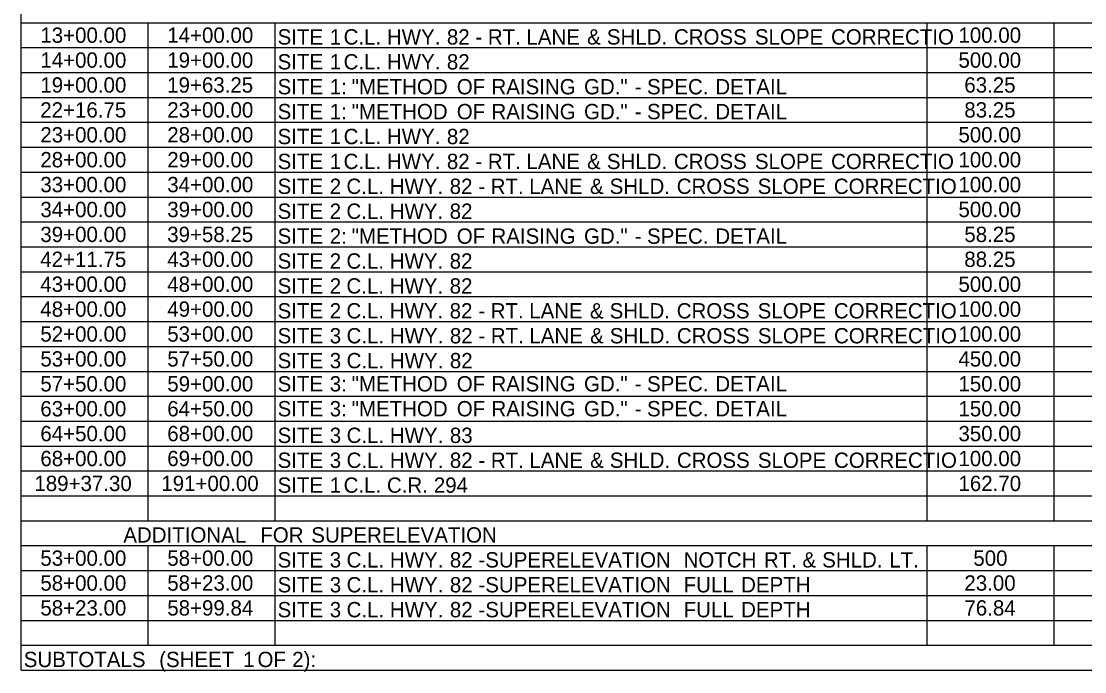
# Model space of a CAD drawing. Extents: x 977434 to 989596, y 1525697 to 1528336.
# Drawn here: x 982704.7 to 983038, y 1527610 to 1527813.7 of the extents above; entities that cross this region are included whole.
import ezdxf

# ---------------------------------------------------------------- set-up
doc = ezdxf.new("R2010")
doc.units = 0
doc.layers.add('Default', color=7, linetype='Continuous')

msp = doc.modelspace()

# ---------------------------------------------------------------- linework, layer by layer
at = {"layer": 'Default'}
for p, q in [((982704.74, 1527610.44), (982704.74, 1528101.06)), ((982704.74, 1527610.44), (982704.74, 1528101.06)), ((982704.74, 1527813.24), (984062.72, 1527813.24)), ((982744.52, 1527657.24), (982744.52, 1527813.24)), ((982744.52, 1527657.24), (982744.52, 1527813.24)), ((982784.3, 1527813.24), (982988.66, 1527813.24)), ((982784.3, 1527657.24), (982784.3, 1527813.24)), ((982784.3, 1527657.24), (982784.3, 1527813.24)), ((982988.66, 1527657.24), (982988.66, 1527813.24)), ((982988.66, 1527657.24), (982988.66, 1527813.24)), ((983028.44, 1527657.24), (983028.44, 1527813.24)), ((983028.44, 1527657.24), (983028.44, 1527813.24)), ((982704.74, 1527805.44), (984062.72, 1527805.44)), ((982704.74, 1527797.64), (984062.72, 1527797.64)), ((982704.74, 1527789.84), (984062.72, 1527789.84)), ((982704.74, 1527782.04), (984062.72, 1527782.04)), ((982704.74, 1527774.24), (984062.72, 1527774.24)), ((982704.74, 1527766.44), (984062.72, 1527766.44)), ((982704.74, 1527758.64), (984062.72, 1527758.64)), ((982704.74, 1527750.84), (984062.72, 1527750.84)), ((982704.74, 1527743.04), (984062.72, 1527743.04)), ((982704.74, 1527735.24), (984062.72, 1527735.24)), ((982704.74, 1527727.44), (984062.72, 1527727.44)), ((982704.74, 1527719.64), (984062.72, 1527719.64)), ((982704.74, 1527711.84), (984062.72, 1527711.84)), ((982704.74, 1527704.04), (984062.72, 1527704.04)), ((982704.74, 1527696.24), (984062.72, 1527696.24)), ((982704.74, 1527688.44), (984062.72, 1527688.44)), ((982704.74, 1527680.64), (984062.72, 1527680.64)), ((982704.74, 1527672.84), (984062.72, 1527672.84)), ((982704.74, 1527665.04), (984062.72, 1527665.04)), ((982704.74, 1527657.24), (983108, 1527657.24)), ((982704.74, 1527657.24), (984062.72, 1527657.24)), ((982704.74, 1527649.44), (984062.72, 1527649.44)), ((982744.52, 1527618.24), (982744.52, 1527649.44)), ((982744.52, 1527618.24), (982744.52, 1527649.44)), ((982784.3, 1527618.24), (982784.3, 1527649.44)), ((982784.3, 1527618.24), (982784.3, 1527649.44)), ((982988.66, 1527618.24), (982988.66, 1527649.44)), ((982988.66, 1527618.24), (982988.66, 1527649.44)), ((983028.44, 1527618.24), (983028.44, 1527649.44)), ((983028.44, 1527618.24), (983028.44, 1527649.44)), ((982704.74, 1527641.64), (984062.72, 1527641.64)), ((982704.74, 1527633.84), (984062.72, 1527633.84)), ((982704.74, 1527626.04), (984062.72, 1527626.04)), ((982704.74, 1527618.24), (984062.72, 1527618.24)), ((982704.74, 1527610.44), (984062.72, 1527610.44))]:
    msp.add_line(p, q, dxfattribs=at)

# ---------------------------------------------------------------- texts
for s, p in [('13+00.00', (982710.72, 1527806.94)), ('14+00.00', (982750.5, 1527806.94)), ('SITE', (982785.08, 1527806.4)), (' C.L.', (982803.99, 1527806.4)), (' 82', (982836.35, 1527806.4)), (' SHLD.', (982886.48, 1527806.4)), (' CROSS', (982907.51, 1527806.4)), (' SLOPE', (982932.88, 1527806.4)), (' CORRECTIO', (982956.75, 1527806.4)), ('100.00', (982998.46, 1527806.94)), (' 1', (982799.63, 1527806.4)), (' HWY.', (982817.56, 1527806.4)), (' -', (982845.31, 1527806.4)), (' RT.', (982849.2, 1527806.4)), (' LANE', (982861.28, 1527806.4)), (' &', (982880.3, 1527806.4)), ('14+00.00', (982710.72, 1527799.14)), ('19+00.00', (982750.5, 1527799.14)), ('SITE', (982785.08, 1527798.6)), (' 1', (982799.63, 1527798.6)), (' C.L.', (982803.99, 1527798.6)), (' HWY.', (982817.56, 1527798.6)), (' 82', (982836.35, 1527798.6)), ('500.00', (982998.46, 1527799.14)), ('19+00.00', (982710.72, 1527791.34)), ('19+63.25', (982750.47, 1527791.34)), ('SITE', (982785.08, 1527790.8)), (' 1:', (982799.63, 1527790.8)), (' "METHOD', (982806.5, 1527790.8)), (' OF', (982839.45, 1527790.8)), (' RAISING', (982850.32, 1527790.8)), (' GD."', (982879.33, 1527790.8)), (' SPEC.', (982899.07, 1527790.8)), (' DETAIL', (982920.48, 1527790.8)), ('63.25', (983000.3, 1527791.34)), (' -', (982895.19, 1527790.8)), ('22+16.75', (982710.69, 1527783.54)), ('23+00.00', (982750.5, 1527783.54)), ('83.25', (983000.3, 1527783.54)), ('SITE', (982785.08, 1527783)), (' 1:', (982799.63, 1527783)), (' "METHOD', (982806.5, 1527783)), (' OF', (982839.45, 1527783)), (' RAISING', (982850.32, 1527783)), (' GD."', (982879.33, 1527783)), (' -', (982895.19, 1527783)), (' SPEC.', (982899.07, 1527783)), (' DETAIL', (982920.48, 1527783)), ('23+00.00', (982710.72, 1527775.74)), ('28+00.00', (982750.5, 1527775.74)), ('SITE', (982785.08, 1527775.2)), (' 1', (982799.63, 1527775.2)), (' C.L.', (982803.99, 1527775.2)), (' HWY.', (982817.56, 1527775.2)), (' 82', (982836.35, 1527775.2)), ('500.00', (982998.46, 1527775.74)), ('28+00.00', (982710.72, 1527767.94)), ('29+00.00', (982750.5, 1527767.94)), ('SITE', (982785.08, 1527767.4)), (' 1', (982799.63, 1527767.4)), (' C.L.', (982803.99, 1527767.4)), (' HWY.', (982817.56, 1527767.4)), (' 82', (982836.35, 1527767.4)), (' RT.', (982849.2, 1527767.4)), (' LANE', (982861.28, 1527767.4)), (' &', (982880.3, 1527767.4)), (' SHLD.', (982886.48, 1527767.4)), (' CROSS', (982907.51, 1527767.4)), (' SLOPE', (982932.88, 1527767.4)), (' CORRECTIO', (982956.75, 1527767.4)), ('100.00', (982998.46, 1527767.94)), (' -', (982845.31, 1527767.4)), ('33+00.00', (982710.72, 1527760.14)), ('34+00.00', (982750.5, 1527760.14)), ('100.00', (982998.46, 1527760.14)), ('SITE', (982785.08, 1527759.6)), (' 2', (982799.63, 1527759.6)), (' C.L.', (982804.87, 1527759.6)), (' HWY.', (982818.44, 1527759.6)), (' 82', (982837.22, 1527759.6)), (' -', (982846.19, 1527759.6)), (' RT.', (982850.07, 1527759.6)), (' LANE', (982862.15, 1527759.6)), (' &', (982881.18, 1527759.6)), (' SHLD.', (982887.36, 1527759.6)), (' CROSS', (982908.39, 1527759.6)), (' SLOPE', (982933.76, 1527759.6)), (' CORRECTIO', (982957.63, 1527759.6)), ('34+00.00', (982710.72, 1527752.34)), ('39+00.00', (982750.5, 1527752.34)), ('SITE', (982785.08, 1527751.8)), (' 2', (982799.63, 1527751.8)), (' C.L.', (982804.87, 1527751.8)), (' HWY.', (982818.44, 1527751.8)), (' 82', (982837.22, 1527751.8)), ('500.00', (982998.46, 1527752.34)), ('39+00.00', (982710.72, 1527744.54)), ('39+58.25', (982750.47, 1527744.54)), ('SITE', (982785.08, 1527744)), (' 2:', (982799.63, 1527744)), (' "METHOD', (982806.5, 1527744)), (' OF', (982839.45, 1527744)), (' RAISING', (982850.32, 1527744)), (' GD."', (982879.33, 1527744)), (' SPEC.', (982899.07, 1527744)), (' DETAIL', (982920.48, 1527744)), ('58.25', (983000.3, 1527744.54)), (' -', (982895.19, 1527744)), ('42+11.75', (982710.69, 1527736.74)), ('43+00.00', (982750.5, 1527736.74)), ('88.25', (983000.3, 1527736.74)), ('SITE', (982785.08, 1527736.2)), (' 2', (982799.63, 1527736.2)), (' C.L.', (982804.87, 1527736.2)), (' HWY.', (982818.44, 1527736.2)), (' 82', (982837.22, 1527736.2)), ('43+00.00', (982710.72, 1527728.94)), ('48+00.00', (982750.5, 1527728.94)), ('SITE', (982785.08, 1527728.4)), (' 2', (982799.63, 1527728.4)), (' C.L.', (982804.87, 1527728.4)), (' HWY.', (982818.44, 1527728.4)), (' 82', (982837.22, 1527728.4)), ('500.00', (982998.46, 1527728.94)), ('48+00.00', (982710.72, 1527721.14)), ('49+00.00', (982750.5, 1527721.14)), ('SITE', (982785.08, 1527720.6)), (' 2', (982799.63, 1527720.6)), (' C.L.', (982804.87, 1527720.6)), (' HWY.', (982818.44, 1527720.6)), (' 82', (982837.22, 1527720.6)), (' RT.', (982850.07, 1527720.6)), (' LANE', (982862.15, 1527720.6)), (' &', (982881.18, 1527720.6)), (' SHLD.', (982887.36, 1527720.6)), (' CROSS', (982908.39, 1527720.6)), (' SLOPE', (982933.76, 1527720.6)), (' CORRECTIO', (982957.63, 1527720.6)), ('100.00', (982998.46, 1527721.14)), (' -', (982846.19, 1527720.6)), ('52+00.00', (982710.72, 1527713.34)), ('53+00.00', (982750.5, 1527713.34)), ('100.00', (982998.46, 1527713.34)), ('SITE', (982785.08, 1527712.8)), (' 3', (982799.63, 1527712.8)), (' C.L.', (982804.92, 1527712.8)), (' HWY.', (982818.49, 1527712.8)), (' 82', (982837.28, 1527712.8)), (' -', (982846.24, 1527712.8)), (' RT.', (982850.12, 1527712.8)), (' LANE', (982862.21, 1527712.8)), (' &', (982881.23, 1527712.8)), (' SHLD.', (982887.41, 1527712.8)), (' CROSS', (982908.44, 1527712.8)), (' SLOPE', (982933.81, 1527712.8)), (' CORRECTIO', (982957.68, 1527712.8)), ('53+00.00', (982710.72, 1527705.54)), ('57+50.00', (982750.5, 1527705.54)), ('SITE', (982785.08, 1527705)), (' 3', (982799.63, 1527705)), (' C.L.', (982804.92, 1527705)), (' HWY.', (982818.49, 1527705)), (' 82', (982837.28, 1527705)), ('450.00', (982998.46, 1527705.54)), ('57+50.00', (982710.72, 1527697.74)), ('59+00.00', (982750.5, 1527697.74)), ('SITE', (982785.08, 1527697.74)), (' 3:', (982799.63, 1527697.74)), (' "METHOD', (982806.5, 1527697.74)), (' OF', (982839.45, 1527697.74)), (' RAISING', (982850.32, 1527697.74)), (' GD."', (982879.33, 1527697.74)), (' SPEC.', (982899.07, 1527697.74)), (' DETAIL', (982920.48, 1527697.74)), ('150.00', (982998.46, 1527697.74)), (' -', (982895.19, 1527697.74)), ('63+00.00', (982710.72, 1527689.94)), ('64+50.00', (982750.5, 1527689.94)), ('SITE', (982785.08, 1527689.94)), (' 3:', (982799.63, 1527689.94)), (' "METHOD', (982806.5, 1527689.94)), (' OF', (982839.45, 1527689.94)), (' RAISING', (982850.32, 1527689.94)), (' GD."', (982879.33, 1527689.94)), (' SPEC.', (982899.07, 1527689.94)), (' DETAIL', (982920.48, 1527689.94)), ('150.00', (982998.46, 1527689.94)), (' -', (982895.19, 1527689.94)), ('64+50.00', (982710.72, 1527682.14)), ('68+00.00', (982750.5, 1527682.14)), ('SITE', (982785.08, 1527681.6)), (' 3', (982799.63, 1527681.6)), (' C.L.', (982804.92, 1527681.6)), (' HWY.', (982818.49, 1527681.6)), (' 83', (982837.28, 1527681.6)), ('350.00', (982998.46, 1527682.14)), ('68+00.00', (982710.72, 1527674.34)), ('69+00.00', (982750.5, 1527674.34)), ('SITE', (982785.08, 1527673.8)), (' 3', (982799.63, 1527673.8)), (' C.L.', (982804.92, 1527673.8)), (' HWY.', (982818.49, 1527673.8)), (' 82', (982837.28, 1527673.8)), (' RT.', (982850.12, 1527673.8)), (' LANE', (982862.21, 1527673.8)), (' &', (982881.23, 1527673.8)), (' SHLD.', (982887.41, 1527673.8)), (' CROSS', (982908.44, 1527673.8)), (' SLOPE', (982933.81, 1527673.8)), (' CORRECTIO', (982957.68, 1527673.8)), ('100.00', (982998.46, 1527674.34)), (' -', (982846.24, 1527673.8)), ('189+37.30', (982708.85, 1527666.54)), ('191+00.00', (982748.63, 1527666.54)), ('162.70', (982998.46, 1527666.54)), ('SITE', (982785.08, 1527666)), (' 1', (982799.63, 1527666)), (' C.L.', (982803.99, 1527666)), (' C.R.', (982817.56, 1527666)), (' 294', (982832.25, 1527666)), ('ADDITIONAL', (982736.72, 1527650.4)), (' FOR', (982777.87, 1527650.4)), (' SUPERELEVATION', (982793.86, 1527650.4)), ('53+00.00', (982710.72, 1527643.14)), ('58+00.00', (982750.5, 1527643.14)), ('500', (983003.12, 1527643.14)), ('SITE', (982785.08, 1527642.6)), (' 3', (982799.63, 1527642.6)), (' C.L.', (982804.92, 1527642.6)), (' HWY.', (982818.49, 1527642.6)), (' 82', (982837.28, 1527642.6)), (' -SUPERELEVATION', (982846.24, 1527642.6)), (' NOTCH', (982910.54, 1527642.6)), (' RT.', (982935.71, 1527642.6)), (' &', (982947.79, 1527642.6)), (' SHLD.', (982953.97, 1527642.6)), (' LT.', (982975, 1527642.6)), ('58+00.00', (982710.72, 1527635.34)), ('58+23.00', (982750.5, 1527635.34)), ('SITE', (982785.08, 1527634.8)), (' 3', (982799.63, 1527634.8)), (' C.L.', (982804.92, 1527634.8)), (' HWY.', (982818.49, 1527634.8)), (' 82', (982837.28, 1527634.8)), (' -SUPERELEVATION', (982846.24, 1527634.8)), (' FULL', (982910.54, 1527634.8)), (' DEPTH', (982928.56, 1527634.8)), ('23.00', (983000.32, 1527635.34)), ('58+23.00', (982710.72, 1527627.54)), ('58+99.84', (982750.5, 1527627.54)), ('SITE', (982785.08, 1527627)), (' 3', (982799.63, 1527627)), (' C.L.', (982804.92, 1527627)), (' HWY.', (982818.49, 1527627)), (' 82', (982837.28, 1527627)), (' -SUPERELEVATION', (982846.24, 1527627)), (' FULL', (982910.54, 1527627)), (' DEPTH', (982928.56, 1527627)), ('76.84', (983000.33, 1527627.54)), ('SUBTOTALS', (982705.52, 1527611.4)), (' (SHEET', (982746.18, 1527611.4)), (' 1', (982772.5, 1527611.4)), (' OF', (982777, 1527611.4)), (' 2):', (982787.87, 1527611.4))]:
    msp.add_text(s, height=4.8, dxfattribs=at).set_placement(p)

doc.saveas('drawing.dxf')
